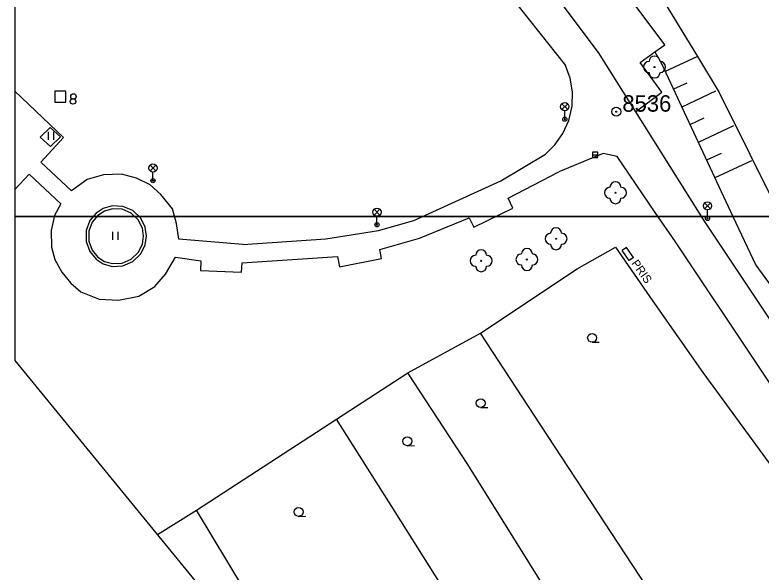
# Model space of a CAD drawing. Extents: x -492431 to -49218, y -1127123 to -112687.
# Drawn here: x -492431 to -492363, y -1127032.4 to -1126981.6 of the extents above; entities that cross this region are included whole.
import ezdxf

# ---------------------------------------------------------------- set-up
doc = ezdxf.new("R2010")
doc.units = 0
for name, color, linetype in [('Vrstva 1', 7, 'Continuous'), ('Vrstva 10', 7, 'Continuous'), ('Vrstva 11', 7, 'Continuous'), ('Vrstva 14', 7, 'Continuous'), ('Vrstva 15', 7, 'Continuous'), ('Vrstva 21', 7, 'Continuous'), ('Vrstva 22', 7, 'Continuous'), ('Vrstva 24', 7, 'Continuous'), ('Vrstva 26', 7, 'Continuous'), ('Vrstva 27', 7, 'Continuous'), ('Vrstva 28', 7, 'Continuous'), ('Vrstva 33', 7, 'Continuous'), ('Vrstva 36', 7, 'Continuous'), ('Vrstva 42', 7, 'Continuous'), ('Vrstva 60', 7, 'Continuous'), ('Vrstva 63', 7, 'Continuous'), ('Vrstva 7', 7, 'Continuous')]:
    doc.layers.add(name, color=color, linetype=linetype)

msp = doc.modelspace()

# ---------------------------------------------------------------- linework, layer by layer
at = {"layer": 'Vrstva 1'}
msp.add_lwpolyline([(-492431.031, -1126895.427), (-492431.031, -1127013.124), (-492341.24, -1127122.91)], dxfattribs=at)
at = {"layer": 'Vrstva 10'}
for p, q in [((-492385.59, -1126974.79), (-492377.87, -1126985.06)), ((-492389.47, -1126975.35), (-492380.84, -1126986.26)), ((-492431.031, -1126988.583), (-492426.6, -1126992.81)), ((-492426.6, -1126992.81), (-492428.67, -1126995.07)), ((-492386.76, -1126996.77), (-492382.68, -1126994.34)), ((-492428.67, -1126995.07), (-492425.87, -1126997.68)), ((-492431.031, -1126997.538), (-492429.72, -1126996.17)), ((-492429.72, -1126996.17), (-492426.85, -1126998.85)), ((-492386.09, -1126998.33), (-492381.47, -1126995.94)), ((-492394.67, -1127000.37), (-492386.76, -1126996.77)), ((-492385.65, -1126999.25), (-492386.09, -1126998.33)), ((-492389.2, -1127000.99), (-492385.65, -1126999.25)), ((-492394.17, -1127001.99), (-492389.64, -1127000.13)), ((-492389.64, -1127000.13), (-492389.2, -1127000.99)), ((-492397.89, -1127001.3), (-492394.67, -1127000.37)), ((-492402.7, -1127002.06), (-492397.89, -1127001.3)), ((-492410.27, -1127002.57), (-492416.09, -1127002.08)), ((-492410.27, -1127002.57), (-492402.7, -1127002.06)), ((-492397.76, -1127003.03), (-492394.17, -1127001.99)), ((-492410.32, -1127004.24), (-492401.63, -1127003.66)), ((-492401.63, -1127003.66), (-492401.45, -1127004.59)), ((-492397.62, -1127003.84), (-492397.76, -1127003.03)), ((-492416.4, -1127003.72), (-492414.1, -1127004.04)), ((-492414.1, -1127004.04), (-492414.11, -1127004.94)), ((-492410.39, -1127005.1), (-492410.32, -1127004.24)), ((-492401.45, -1127004.59), (-492397.62, -1127003.84)), ((-492414.11, -1127004.94), (-492410.39, -1127005.1))]:
    msp.add_line(p, q, dxfattribs=at)
for points in [[(-492377.87, -1126985.06), (-492374.48, -1126990.46), (-492368.22, -1127000.44)], [(-492382.68, -1126994.34), (-492381.82, -1126993.49), (-492381.09, -1126992.44), (-492380.56, -1126991.25), (-492380.26, -1126989.96), (-492380.22, -1126988.66), (-492380.43, -1126987.4), (-492380.84, -1126986.26)], [(-492376.14, -1126994.55), (-492377.42, -1126994.27), (-492381.47, -1126995.94)], [(-492370.84, -1127002.32), (-492372.67, -1126999.64), (-492376.14, -1126994.55)], [(-492421.32, -1126996.15), (-492422.96, -1126996.22), (-492424.44, -1126996.63)], [(-492418.72, -1126997.14), (-492419.94, -1126996.53), (-492421.32, -1126996.15)], [(-492424.44, -1126996.63), (-492425.32, -1126997.27), (-492425.87, -1126997.68)], [(-492416.67, -1126999.32), (-492417.72, -1126998.02), (-492418.72, -1126997.14)], [(-492426.85, -1126998.85), (-492427.41, -1126999.92), (-492427.73, -1127001.3), (-492427.69, -1127002.8)], [(-492416.09, -1127002.08), (-492416.31, -1127000.66), (-492416.67, -1126999.32)], [(-492368.22, -1127000.44), (-492338.22, -1127045.43)], [(-492340.83, -1127047.27), (-492370.84, -1127002.32)], [(-492427.69, -1127002.8), (-492427.4, -1127003.94), (-492426.77, -1127005.09), (-492425.93, -1127006.1)], [(-492418.28, -1127006.4), (-492417.3, -1127005.28), (-492416.4, -1127003.72)], [(-492425.93, -1127006.1), (-492425.02, -1127006.87), (-492423.34, -1127007.54), (-492421.6, -1127007.65)], [(-492421.6, -1127007.65), (-492419.73, -1127007.26), (-492418.28, -1127006.4)]]:
    msp.add_lwpolyline(points, dxfattribs=at)
at = {"layer": 'Vrstva 11'}
for p, q in [((-492428.74, -1126992.77), (-492427.82, -1126991.89)), ((-492427.82, -1126991.89), (-492426.87, -1126992.76)), ((-492428.74, -1126992.77), (-492427.79, -1126993.64)), ((-492427.79, -1126993.64), (-492426.87, -1126992.76))]:
    msp.add_line(p, q, dxfattribs=at)
for points in [[(-492419.04, -1127001.8), (-492419.16, -1127000.99), (-492419.57, -1127000.17), (-492420.29, -1126999.48), (-492421.21, -1126999.09), (-492422.16, -1126999.04), (-492422.98, -1126999.27), (-492423.64, -1126999.7), (-492424.21, -1127000.38), (-492424.55, -1127001.3), (-492424.55, -1127002.3), (-492424.21, -1127003.21), (-492423.64, -1127003.9), (-492422.98, -1127004.33), (-492422.16, -1127004.56), (-492421.21, -1127004.51), (-492420.29, -1127004.12), (-492419.57, -1127003.43), (-492419.16, -1127002.61), (-492419.04, -1127001.8)], [(-492419.31, -1127001.81), (-492419.41, -1127001.08), (-492419.79, -1127000.33), (-492420.44, -1126999.71), (-492421.27, -1126999.35), (-492422.13, -1126999.31), (-492422.88, -1126999.52), (-492423.48, -1126999.91), (-492424, -1127000.53), (-492424.3, -1127001.35), (-492424.3, -1127002.26), (-492424, -1127003.09), (-492423.48, -1127003.71), (-492422.88, -1127004.1), (-492422.13, -1127004.31), (-492421.27, -1127004.27), (-492420.44, -1127003.91), (-492419.79, -1127003.29), (-492419.41, -1127002.54), (-492419.31, -1127001.81)], [(-492370.82, -1127037.75), (-492383.12, -1127019)], [(-492375.63, -1127045.24), (-492389.76, -1127022.63)], [(-492385.37, -1127044.39), (-492396.38, -1127026.94)]]:
    msp.add_lwpolyline(points, dxfattribs=at)
at = {"layer": 'Vrstva 14'}
for points in [[(-492395.24, -1126948.66), (-492390.84, -1126952.8), (-492387.07, -1126958.27), (-492383.84, -1126963.55), (-492382.16, -1126965.51), (-492378.51, -1126971.37), (-492371.92, -1126980.36), (-492368.82, -1126985.42), (-492366.86, -1126988.7), (-492361.24, -1127000)], [(-492372.7, -1126985.01), (-492372.15, -1126986.01), (-492365.6, -1127000)], [(-492365.6, -1127000), (-492363.51, -1127004.45), (-492350.74, -1127021.91)]]:
    msp.add_lwpolyline(points, dxfattribs=at)
at = {"layer": 'Vrstva 15'}
for p, q in [((-492368.82, -1126985.42), (-492371.78, -1126986.81)), ((-492369.81, -1126987.85), (-492371.02, -1126988.42)), ((-492367.18, -1126988.59), (-492370.26, -1126990.04)), ((-492368.25, -1126991.06), (-492369.51, -1126991.65)), ((-492365.54, -1126991.76), (-492368.75, -1126993.27)), ((-492366.68, -1126994.27), (-492367.99, -1126994.88)), ((-492363.89, -1126994.93), (-492367.24, -1126996.5))]:
    msp.add_line(p, q, dxfattribs=at)
at = {"layer": 'Vrstva 21'}
msp.add_lwpolyline([(-492374.48, -1126990.46), (-492372.08, -1126988.68), (-492374.06, -1126985.99), (-492372.7, -1126985.01), (-492371.81, -1126984.37), (-492382.24, -1126970.36), (-492386.2, -1126963.71), (-492392.1, -1126954.16), (-492397.63, -1126947.14), (-492399.91, -1126946.01)], dxfattribs=at)
at = {"layer": 'Vrstva 22'}
for centre in [(-492372.74, -1126986.39), (-492376.3, -1126997.85), (-492381.71, -1127002.04), (-492388.54, -1127004.05), (-492384.37, -1127003.93)]:
    msp.add_circle(centre, 0.05, dxfattribs=at)
for centre, start, end in [((-492373.24, -1126986.39), 90, 270), ((-492372.74, -1126985.89), 360, 180), ((-492372.24, -1126986.39), 270, 90), ((-492372.74, -1126986.89), 180, 0), ((-492376.3, -1126997.35), 360, 180), ((-492376.8, -1126997.85), 90, 270), ((-492375.8, -1126997.85), 270, 90), ((-492376.3, -1126998.35), 180, 0), ((-492382.21, -1127002.04), 90, 270), ((-492381.71, -1127001.54), 360, 180), ((-492381.21, -1127002.04), 270, 90), ((-492384.37, -1127003.43), 360, 180), ((-492381.71, -1127002.54), 180, 0), ((-492389.04, -1127004.05), 90, 270), ((-492388.54, -1127003.55), 360, 180), ((-492388.04, -1127004.05), 270, 90), ((-492384.87, -1127003.93), 90, 270), ((-492383.87, -1127003.93), 270, 90), ((-492388.54, -1127004.55), 180, 0), ((-492384.37, -1127004.43), 180, 0)]:
    msp.add_arc(centre, 0.5, start, end, dxfattribs=at)
at = {"layer": 'Vrstva 24'}
for p, q in [((-492375.29, -1127002.83), (-492375.7, -1127003.12)), ((-492374.65, -1127003.74), (-492375.29, -1127002.83)), ((-492375.06, -1127004.03), (-492375.7, -1127003.12)), ((-492374.65, -1127003.74), (-492375.06, -1127004.03))]:
    msp.add_line(p, q, dxfattribs=at)
at = {"layer": 'Vrstva 26'}
msp.add_lwpolyline([(-492427.39, -1126989.59), (-492426.39, -1126989.59), (-492426.39, -1126988.59), (-492427.39, -1126988.59)], close=True, dxfattribs=at)
at = {"layer": 'Vrstva 27'}
msp.add_line((-492378.4, -1126994.39), (-492377.9, -1126994.39), dxfattribs=at)
msp.add_lwpolyline([(-492378.4, -1126994.64), (-492377.9, -1126994.64), (-492377.9, -1126994.14), (-492378.4, -1126994.14)], close=True, dxfattribs=at)
at = {"layer": 'Vrstva 28'}
for centre in [(-492425.74, -1126989.53), (-492425.7, -1126989.07)]:
    msp.add_circle(centre, 0.25, dxfattribs=at)
at = {"layer": 'Vrstva 33'}
for p, q in [((-492381.185, -1126989.735), (-492380.655, -1126990.265)), ((-492381.185, -1126990.265), (-492380.655, -1126989.735)), ((-492380.92, -1126991.15), (-492380.92, -1126990.375)), ((-492418.715, -1126995.335), (-492418.185, -1126995.865)), ((-492418.715, -1126995.865), (-492418.185, -1126995.335)), ((-492418.45, -1126996.75), (-492418.45, -1126995.975)), ((-492368.175, -1126998.775), (-492367.645, -1126999.305)), ((-492368.175, -1126999.305), (-492367.645, -1126998.775)), ((-492398.305, -1126999.355), (-492397.775, -1126999.885)), ((-492398.305, -1126999.885), (-492397.775, -1126999.355)), ((-492367.91, -1127000.19), (-492367.91, -1126999.415)), ((-492398.04, -1127000.77), (-492398.04, -1126999.995))]:
    msp.add_line(p, q, dxfattribs=at)
for centre, radius in [((-492380.92, -1126990), 0.375), ((-492380.92, -1126991.15), 0.19), ((-492380.92, -1126991.15), 0.05), ((-492418.45, -1126995.6), 0.375), ((-492418.45, -1126996.75), 0.19), ((-492418.45, -1126996.75), 0.05), ((-492367.91, -1126999.04), 0.375), ((-492398.04, -1126999.62), 0.375), ((-492367.91, -1127000.19), 0.19), ((-492367.91, -1127000.19), 0.05), ((-492398.04, -1127000.77), 0.19), ((-492398.04, -1127000.77), 0.05)]:
    msp.add_circle(centre, radius, dxfattribs=at)
at = {"layer": 'Vrstva 36'}
for p, q in [((-492427.98, -1126993.04), (-492427.98, -1126992.29)), ((-492427.48, -1126993.04), (-492427.48, -1126992.29)), ((-492422.12, -1127002.15), (-492422.12, -1127001.4)), ((-492421.62, -1127002.15), (-492421.62, -1127001.4)), ((-492378.432, -1127011.48), (-492377.782, -1127011.477)), ((-492388.582, -1127017.43), (-492387.932, -1127017.427)), ((-492395.272, -1127020.9), (-492394.622, -1127020.897)), ((-492405.172, -1127027.34), (-492404.522, -1127027.337))]:
    msp.add_line(p, q, dxfattribs=at)
for centre in [(-492378.432, -1127011.077), (-492388.582, -1127017.027), (-492395.272, -1127020.497), (-492405.172, -1127026.937)]:
    msp.add_circle(centre, 0.403, dxfattribs=at)
at = {"layer": 'Vrstva 60'}
for p, q in [((-492431.031, -1127000), (-492166.731, -1127000)), ((-492166.731, -1127000), (-492431.031, -1127000))]:
    msp.add_line(p, q, dxfattribs=at)
for points in [[(-492166.731, -1127000), (-492133.025, -1126976.26), (-492272.695, -1126862.455), (-492313.78, -1126867.2), (-492431.031, -1126895.427), (-492431.031, -1127000)], [(-492431.031, -1127000), (-492431.031, -1127013.124), (-492341.24, -1127122.91), (-492166.731, -1127000)]]:
    msp.add_lwpolyline(points, dxfattribs=at)
at = {"layer": 'Vrstva 63'}
for radius in [0.412, 0.05]:
    msp.add_circle((-492376.23, -1126990.46), radius, dxfattribs=at)
at = {"layer": 'Vrstva 7'}
for p, q in [((-492379.78, -1127004.77), (-492376.3, -1127002.81)), ((-492388.61, -1127010.64), (-492379.78, -1127004.77)), ((-492395.22, -1127014.25), (-492388.61, -1127010.64)), ((-492383.12, -1127019), (-492388.61, -1127010.64)), ((-492401.71, -1127018.48), (-492395.22, -1127014.25)), ((-492389.76, -1127022.63), (-492395.22, -1127014.25)), ((-492414.49, -1127026.79), (-492401.71, -1127018.48)), ((-492396.38, -1127026.94), (-492401.71, -1127018.48)), ((-492418.041, -1127029.006), (-492414.49, -1127026.79)), ((-492409.31, -1127035.34), (-492414.49, -1127026.79))]:
    msp.add_line(p, q, dxfattribs=at)
for points in [[(-492376.3, -1127002.81), (-492372.88, -1127007.72), (-492368.33, -1127014.23)], [(-492368.33, -1127014.23), (-492362.3, -1127022.49)]]:
    msp.add_lwpolyline(points, dxfattribs=at)

# ---------------------------------------------------------------- texts
at = {"layer": 'Vrstva 42'}
msp.add_text('PRIS', height=0.75, rotation=305.11859, dxfattribs=at).set_placement((-492374.877, -1127004.281))
at = {"layer": 'Vrstva 63'}
msp.add_text(' 8536', height=1.5, dxfattribs=at).set_placement((-492376.23, -1126990.46))

doc.saveas('drawing.dxf')
